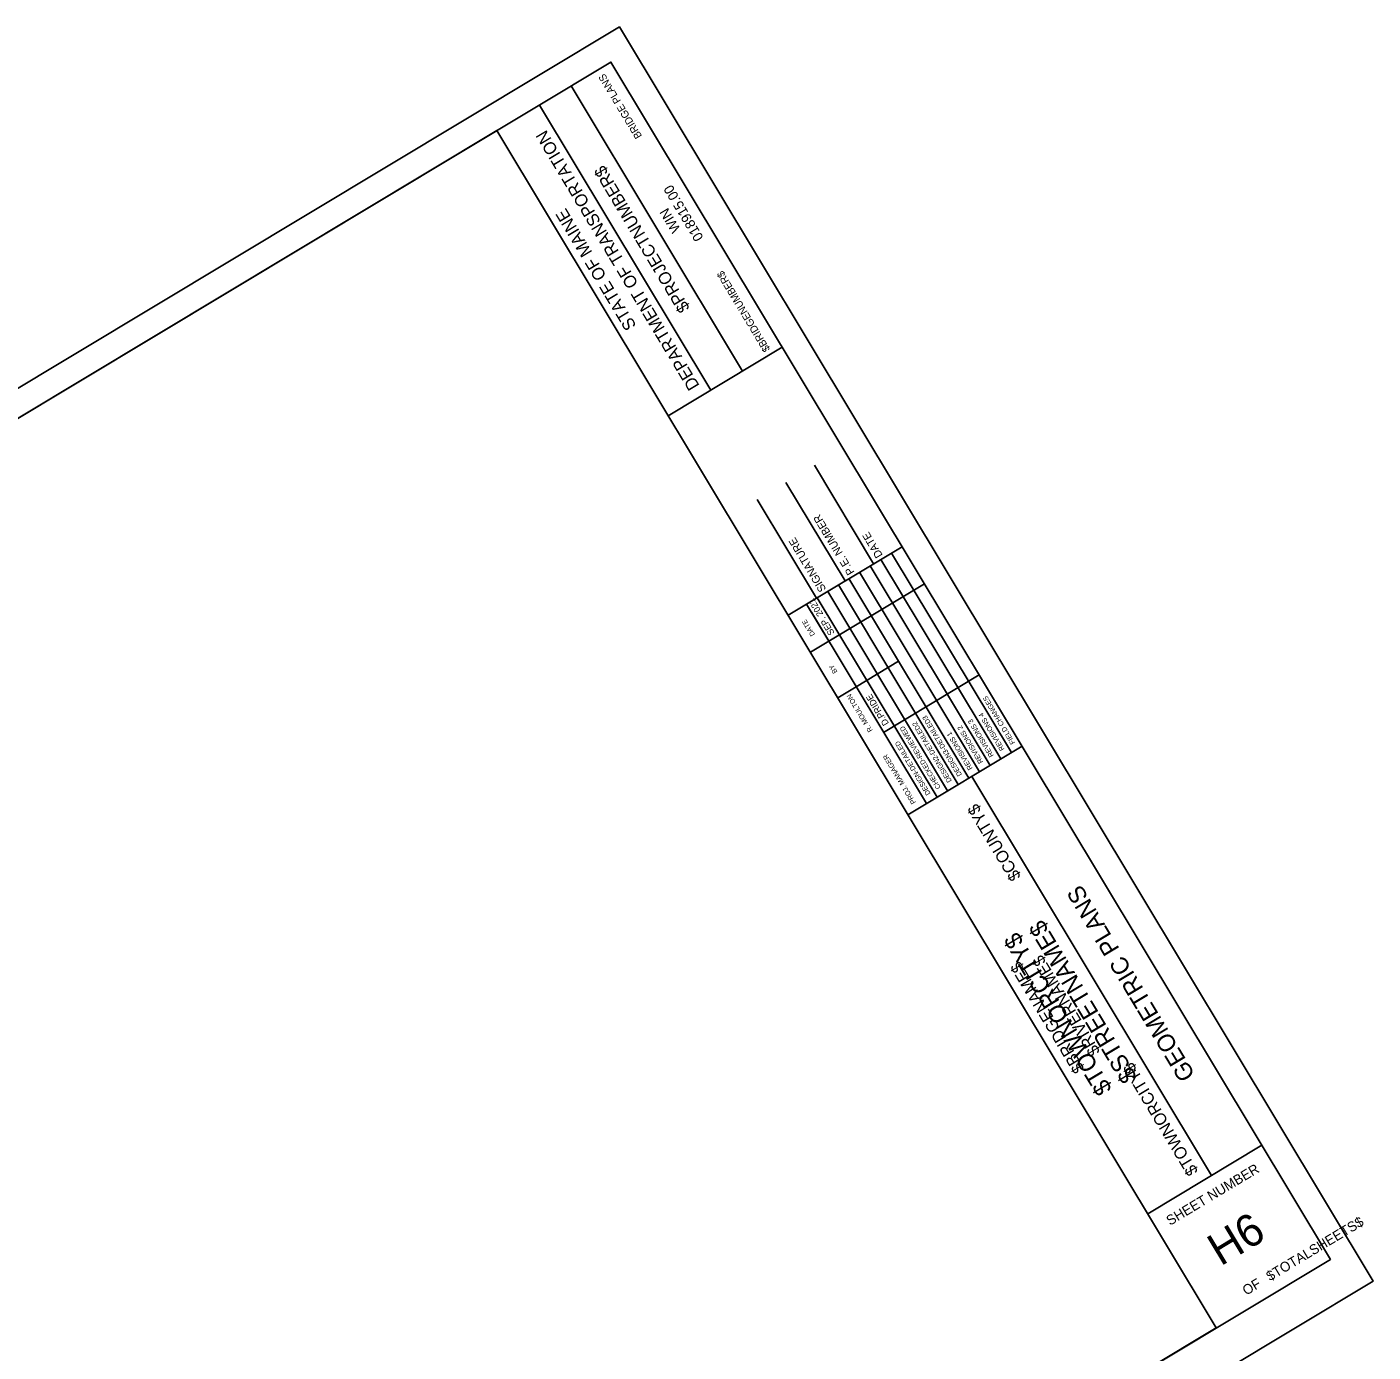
# Model space of a CAD drawing. Extents: x 1745087 to 1746099, y 463334 to 464243.
# Drawn here: x 1745593 to 1746099, y 463745 to 464243 of the extents above; entities that cross this region are included whole.
import ezdxf

# ---------------------------------------------------------------- set-up
doc = ezdxf.new("R2010")
doc.units = 0
for name, color, linetype in [('ANNOTATION', 7, 'Continuous'), ('D_Roadway_Centerline_Flags', 7, 'Continuous'), ('DIMENSIONS', 7, 'Continuous'), ('M_Fencing', 7, 'Continuous'), ('M_Misc_MiscItems', 7, 'Continuous')]:
    doc.layers.add(name, color=color, linetype=linetype)

msp = doc.modelspace()

# ---------------------------------------------------------------- linework, layer by layer
at = {"layer": 'DIMENSIONS'}
for p, q in [((1745861.78, 464114.14), (1745797.4, 464221.29)), ((1745849.8, 464106.94), (1745785.42, 464214.09)), ((1746039.82, 463754.49), (1745769.43, 464204.5)), ((1745833.83, 464097.33), (1745876.68, 464123.08)), ((1745911.01, 464041.68), (1745888.74, 464078.74)), ((1745900.3, 464035.24), (1745878.03, 464072.3)), ((1745889.58, 464028.8), (1745867.31, 464065.87)), ((1745878.87, 464022.37), (1745921.72, 464048.12)), ((1745923.93, 463947.36), (1745966.79, 463973.12)), ((1746038.03, 463811.76), (1745947.89, 463961.76)), ((1746014.06, 463797.36), (1746056.92, 463823.11))]:
    msp.add_line(p, q, dxfattribs=at)
msp.add_lwpolyline([(1745126.55, 463818.22), (1745812.29, 464230.25), (1746082.68, 463780.24), (1745396.95, 463368.21)], close=True, dxfattribs=at)
for points in [[(1745962.79, 463970.73), (1745917.74, 464045.72)], [(1745954.81, 463965.93), (1745909.75, 464040.92)], [(1745958.8, 463968.33), (1745913.74, 464043.32)], [(1745946.82, 463961.13), (1745901.76, 464036.12)], [(1745950.81, 463963.53), (1745905.76, 464038.52)], [(1745887.24, 464008.44), (1745930.09, 464034.19)], [(1745893.78, 464031.33), (1745938.84, 463956.34)], [(1745942.83, 463958.74), (1745897.77, 464033.72)], [(1745894.16, 464012.6), (1745885.79, 464026.52)], [(1745934.84, 463953.94), (1745889.78, 464028.93)], [(1745930.85, 463951.54), (1745887.61, 464023.5)], [(1745904.46, 463995.45), (1745920.43, 464005.05)], [(1745897.54, 463991.29), (1745904.46, 463995.45)], [(1745914.76, 463978.31), (1745950.7, 463999.9)]]:
    msp.add_lwpolyline(points, dxfattribs=at)
at = {"layer": 'M_Fencing'}
msp.add_lwpolyline([(1745370.14, 463334.26), (1746098.73, 463772.04), (1745815.46, 464243.48), (1745086.87, 463805.7)], close=True, dxfattribs=at)
at = {"layer": 'M_Misc_MiscItems'}
msp.add_lwpolyline([(1745126.55, 463818.22), (1745769.43, 464204.5), (1746039.82, 463754.49), (1745396.95, 463368.21)], close=True, dxfattribs=at)

# ---------------------------------------------------------------- texts
at = {"layer": 'ANNOTATION'}
for s, height, p in [('BRIDGE PLANS', 2.795, (1745824.07, 464202.47)), ('$BRIDGENUMBER$', 2.795, (1745872.21, 464122.35)), ('$COUNTY$', 4.536, (1745966.57, 463924.17)), ('$RIVERNAME$', 4.5358, (1745996.33, 463858.35)), ('$BRIDGENAME$', 4.5358, (1745990.47, 463851.83)), ('$TOWNORCITY$', 4.5358, (1746033.16, 463813.35))]:
    msp.add_text(s, height=height, rotation=121, dxfattribs=at).set_placement(p)
at = {"layer": 'D_Roadway_Centerline_Flags'}
for s, p in [('$STREETNAME$', (1746010.27, 463848.91)), ('$TOWNORCITY$', (1746000.86, 463844.31))]:
    msp.add_text(s, height=6.5214, rotation=121, dxfattribs=at).set_placement(p)
at = {"layer": 'DIMENSIONS'}
for s, height, rotation, p in [('DEPARTMENT OF TRANSPORTATION', 4.6588, 121, (1745845.73, 464108.64)), ('$PROJECTNUMBER$', 4.6588, 121, (1745842.12, 464137.81)), ('018915.00', 3.726, 121, (1745847.21, 464164.31)), ('STATE OF MAINE', 4.6588, 121, (1745821.99, 464131.15)), ('WIN', 3.726, 121, (1745838.56, 464167.47)), ('P.E. NUMBER', 2.9528, 121, (1745903.92, 464038.54)), ('SIGNATURE', 2.953, 121, (1745893.29, 464032.15)), ('DATE', 2.953, 121, (1745914.55, 464044.93)), ('SEP. 2021', 2.423, 121, (1745896.43, 464015.69)), ('DATE', 1.857, 121, (1745889.08, 464015.12)), ('BY', 1.857, 121, (1745897.5, 464001.1)), ('R. MOULTON', 1.864, 121, (1745910.72, 463979.1)), ('D.PRIDE', 2.423, 121, (1745916.83, 463981.73)), ('FIELD CHANGES', 1.8637, 121, (1745964.26, 463974.44)), ('REVISIONS 4', 1.8637, 121, (1745960.27, 463972.04)), ('CHECKED-REVIEWED', 1.8637, 121, (1745936.31, 463957.65)), ('DESIGN2-DETAILED2', 1.8637, 121, (1745940.46, 463960.14)), ('DESIGN3-DETAILED3', 1.8637, 121, (1745944.29, 463962.45)), ('REVISIONS 2', 1.8637, 121, (1745952.28, 463967.24)), ('REVISIONS 3', 1.8637, 121, (1745956.27, 463969.64)), ('REVISIONS 1', 1.8637, 121, (1745948.29, 463964.84)), ('PROJ. MANAGER', 1.8637, 121, (1745926.98, 463952.04)), ('DESIGN-DETAILED', 1.8637, 121, (1745932.48, 463955.34)), ('GEOMETRIC PLANS', 6.5214, 121, (1746032.06, 463849.59)), ('SHEET NUMBER', 3.7264, 31, (1746022.42, 463792.83)), ('H6', 12.097, 31, (1746041.41, 463777.5)), ('$TOTALSHEETS$', 3.7264, 31, (1746060, 463771.94)), ('OF', 3.726, 31, (1746051.05, 463766.56))]:
    msp.add_text(s, height=height, rotation=rotation, dxfattribs=at).set_placement(p)

doc.saveas('drawing.dxf')
